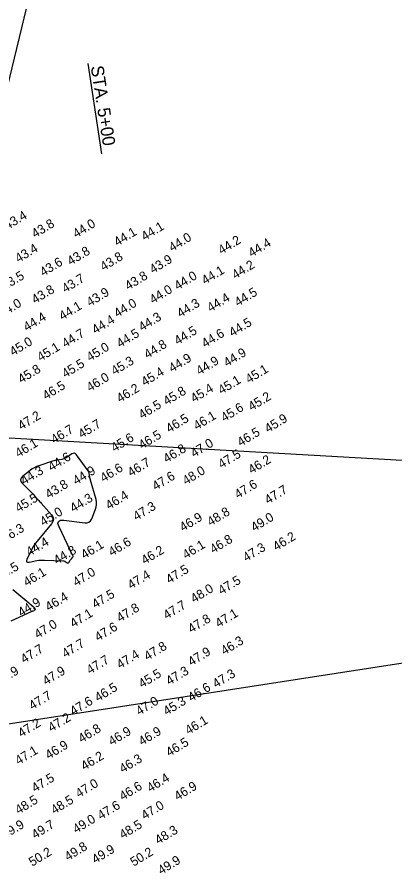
# Model space of a CAD drawing. Extents: x 415488 to 419888, y 1187739 to 1191312.
# Drawn here: x 417516 to 417929, y 1189587 to 1190515 of the extents above; entities that cross this region are included whole.
import ezdxf

# ---------------------------------------------------------------- set-up
doc = ezdxf.new("R2010")
doc.units = 0
for name, color, linetype in [('C-CHAN-POIT', 7, 'Continuous'), ('C-CHAN-WIDE', 7, 'Continuous'), ('V-ALGN-TEXT', 7, 'Continuous'), ('V-TOPO-MAJR', 7, 'Continuous'), ('V-TOPO-SOUN', 7, 'Continuous')]:
    doc.layers.add(name, color=color, linetype=linetype)

msp = doc.modelspace()

# ---------------------------------------------------------------- linework, layer by layer
at = {"layer": 'C-CHAN-POIT'}
msp.add_line((417394.74, 1189724.92), (418985.51, 1189971.03), dxfattribs=at)
at = {"layer": 'C-CHAN-WIDE'}
msp.add_line((416205.49, 1190128.89), (418985.51, 1189971.03), dxfattribs=at)
at = {"layer": 'V-ALGN-TEXT'}
for p, q in [((417252.51, 1189399.35), (417536.93, 1190565.61)), ((417593.74, 1190464.04), (417609.03, 1190365.21))]:
    msp.add_line(p, q, dxfattribs=at)
at = {"layer": 'V-TOPO-MAJR'}
msp.add_lwpolyline([(417596.14, 1190011.22), (417596.09, 1190011.47), (417596.04, 1190011.73), (417595.36, 1190015.86), (417595.2, 1190016.62), (417594.94, 1190017.34), (417594.61, 1190018.03), (417594.19, 1190018.68), (417581.35, 1190036.38), (417580.3, 1190037.46), (417579.14, 1190037.98), (417577.87, 1190037.92), (417576.5, 1190037.28), (417570.09, 1190033.16), (417568.99, 1190032.52), (417567.83, 1190032), (417566.63, 1190031.6), (417565.38, 1190031.33), (417560.3, 1190030.47), (417559.03, 1190030.23), (417557.77, 1190029.95), (417556.53, 1190029.62), (417555.3, 1190029.24), (417540.16, 1190024.36), (417537.65, 1190023.42), (417535.27, 1190022.27), (417533, 1190020.9), (417530.85, 1190019.31), (417522.47, 1190012.53), (417520.88, 1190010.81), (417520.28, 1190009.04), (417520.69, 1190007.21), (417522.09, 1190005.33), (417531.95, 1189995.47), (417532.9, 1189994.5), (417533.84, 1189993.53), (417534.76, 1189992.53), (417535.67, 1189991.53), (417539.27, 1189987.49), (417540.17, 1189986.48), (417541.07, 1189985.47), (417541.97, 1189984.46), (417542.87, 1189983.45), (417554.04, 1189970.89), (417555.67, 1189968.45), (417556.24, 1189966), (417555.75, 1189963.52), (417554.2, 1189961.03), (417538.31, 1189941.95), (417536.64, 1189939.83), (417535.12, 1189937.62), (417533.73, 1189935.32), (417532.48, 1189932.93), (417527.25, 1189922.2), (417526.69, 1189920.56), (417526.9, 1189919.49), (417527.87, 1189919.01), (417529.6, 1189919.1), (417538.07, 1189920.64), (417540.19, 1189920.97), (417542.32, 1189921.17), (417544.46, 1189921.26), (417546.6, 1189921.23), (417567.09, 1189920.4), (417567.67, 1189920.33), (417568.23, 1189920.19), (417568.76, 1189919.97), (417569.27, 1189919.68), (417571.25, 1189918.34), (417571.72, 1189918.1), (417572.16, 1189918.08), (417572.57, 1189918.25), (417572.94, 1189918.63), (417574.67, 1189921.02), (417574.97, 1189921.44), (417575.29, 1189921.84), (417575.61, 1189922.24), (417575.95, 1189922.64), (417577.3, 1189924.19), (417577.57, 1189924.58), (417577.7, 1189925), (417577.69, 1189925.44), (417577.53, 1189925.89), (417562.45, 1189957.46), (417561.25, 1189961.13), (417561.74, 1189963.59), (417563.91, 1189964.82), (417567.78, 1189964.83), (417590.48, 1189961.93), (417593.04, 1189961.94), (417595.17, 1189962.7), (417596.86, 1189964.19), (417598.12, 1189966.43), (417602.29, 1189976.84), (417603.11, 1189979.46), (417603.47, 1189982.1), (417603.39, 1189984.77), (417602.86, 1189987.46), (417596.9, 1190008.74), (417596.83, 1190008.99), (417596.76, 1190009.24), (417596.68, 1190009.49), (417596.6, 1190009.73), (417596.28, 1190010.72), (417596.21, 1190010.97)], close=True, dxfattribs=at)
msp.add_lwpolyline([(417511.83, 1189889.14), (417529.23, 1189874.49), (417529.79, 1189874.02), (417530.35, 1189873.55), (417530.92, 1189873.08), (417531.48, 1189872.61), (417534.31, 1189870.25), (417534.57, 1189870.01), (417534.81, 1189869.76), (417535.03, 1189869.5), (417535.23, 1189869.21), (417536.09, 1189867.85), (417536.19, 1189867.65), (417536.22, 1189867.45), (417536.17, 1189867.26), (417536.07, 1189867.06), (417535.49, 1189866.29), (417535.34, 1189866.11), (417535.16, 1189865.97), (417534.97, 1189865.85), (417534.75, 1189865.76), (417533.57, 1189865.39), (417533.29, 1189865.3), (417533.02, 1189865.2), (417532.76, 1189865.09), (417532.5, 1189864.97), (417509.81, 1189854.42)], dxfattribs=at)

# ---------------------------------------------------------------- texts
at = {"layer": 'V-ALGN-TEXT'}
msp.add_text('STA. 5+00', height=13.92, rotation=278.79434, dxfattribs=at).set_placement((417597.07, 1190460.78))
at = {"layer": 'V-TOPO-SOUN'}
for s, p in [('43.4 ', (417506.09, 1190281.99)), ('43.8 ', (417536.1, 1190273)), ('44.0 ', (417581.09, 1190273)), ('44.1 ', (417656.08, 1190269.98)), ('44.1 ', (417626.1, 1190263.97)), ('44.0 ', (417686.1, 1190257.97)), ('44.2 ', (417740.11, 1190254.98)), ('44.4 ', (417773.08, 1190252)), ('43.4 ', (417518.09, 1190245.99)), ('43.8 ', (417575.08, 1190242.98)), ('43.6 ', (417545.09, 1190230.97)), ('43.8 ', (417611.1, 1190236.97)), ('43.9 ', (417665.11, 1190233.99)), ('44.1 ', (417722.1, 1190221.98)), ('44.2 ', (417755.1, 1190227.98)), ('43.5 ', (417503.1, 1190215.97)), ('43.7 ', (417569.11, 1190212.99)), ('43.8 ', (417638.11, 1190215.97)), ('44.0 ', (417692.11, 1190215.97)), ('43.8 ', (417536.1, 1190200.98)), ('44.0 ', (417665.11, 1190200.98)), ('43.9 ', (417596.08, 1190198)), ('44.4 ', (417728.1, 1190191.99)), ('44.5 ', (417758.09, 1190198)), ('44.0 ', (417500.08, 1190185.99)), ('44.1 ', (417566.09, 1190182.97)), ('44.0 ', (417626.1, 1190185.99)), ('44.3 ', (417695.09, 1190185.99)), ('44.4 ', (417527.08, 1190170.99)), ('44.4 ', (417602.08, 1190167.98)), ('44.3 ', (417653.1, 1190170.99)), ('44.5 ', (417752.08, 1190164.99)), ('44.5 ', (417692.11, 1190155.97)), ('44.7 ', (417569.11, 1190152.98)), ('44.5 ', (417629.08, 1190152.98)), ('44.6 ', (417722.1, 1190152.98)), ('45.0 ', (417512.09, 1190143.99)), ('45.1 ', (417542.11, 1190137.99)), ('45.0 ', (417596.08, 1190137.99)), ('44.8 ', (417659.1, 1190140.98)), ('44.9 ', (417746.08, 1190131.99)), ('45.5 ', (417569.11, 1190119.98)), ('45.3 ', (417623.08, 1190123)), ('44.9 ', (417686.1, 1190125.98)), ('44.9 ', (417716.09, 1190123)), ('45.8 ', (417521.08, 1190113.97)), ('45.4 ', (417656.08, 1190110.99)), ('45.1 ', (417770.09, 1190113.97)), ('46.0 ', (417596.08, 1190104.98)), ('45.1 ', (417740.11, 1190102)), ('46.5 ', (417548.08, 1190095.99)), ('46.2 ', (417629.08, 1190092.98)), ('45.8 ', (417680.1, 1190089.99)), ('45.4 ', (417710.09, 1190092.98)), ('45.2 ', (417773.08, 1190083.99)), ('46.5 ', (417653.1, 1190075)), ('45.6 ', (417743.09, 1190071.98)), ('47.2 ', (417521.08, 1190062.99)), ('46.1 ', (417713.11, 1190062.99)), ('45.7 ', (417587.09, 1190053.97)), ('46.5 ', (417683.09, 1190059.97)), ('45.9 ', (417791.09, 1190059.97)), ('46.7 ', (417557.1, 1190048)), ('46.5 ', (417761.1, 1190044.98)), ('45.6 ', (417623.08, 1190038.97)), ('46.5 ', (417653.1, 1190041.99)), ('46.1 ', (417518.09, 1190032.97)), ('46.8 ', (417680.1, 1190026.97)), ('47.0 ', (417710.09, 1190032.97)), ('44.6 ', (417554.08, 1190017.98)), ('47.5 ', (417740.11, 1190021)), ('46.2 ', (417773.08, 1190014.99)), ('46.6 ', (417611.1, 1190005.97)), ('46.7 ', (417641.09, 1190011.97)), ('44.3 ', (417524.1, 1190002.98)), ('44.9 ', (417581.09, 1190002.98)), ('47.6 ', (417668.09, 1189996.98)), ('48.0 ', (417701.1, 1190002.98)), ('43.8 ', (417551.1, 1189987.99)), ('47.6 ', (417758.09, 1189987.99)), ('47.7 ', (417791.09, 1189981.99)), ('45.5 ', (417518.09, 1189973)), ('44.3 ', (417578.1, 1189973)), ('46.4 ', (417617.11, 1189975.98)), ('47.3 ', (417647.1, 1189963.97)), ('45.0 ', (417545.09, 1189957.97)), ('46.9 ', (417698.08, 1189951.97)), ('48.8 ', (417728.1, 1189957.97)), ('49.0 ', (417776.1, 1189951.97)), ('46.3 ', (417503.1, 1189939.99)), ('44.4 ', (417530.1, 1189925)), ('46.6 ', (417620.09, 1189925)), ('46.8 ', (417731.08, 1189927.98)), ('46.2 ', (417800.08, 1189930.97)), ('44.8 ', (417560.09, 1189915.98)), ('46.1 ', (417590.11, 1189921.98)), ('46.2 ', (417656.08, 1189915.98)), ('46.1 ', (417701.1, 1189921.98)), ('47.3 ', (417767.11, 1189918.99)), ('45.5 ', (417497.1, 1189898)), ('47.5 ', (417683.09, 1189894.98)), ('46.1 ', (417527.08, 1189891.99)), ('47.0 ', (417581.09, 1189891.99)), ('47.4 ', (417641.09, 1189888.97)), ('47.5 ', (417740.11, 1189882.97)), ('47.5 ', (417602.08, 1189867.98)), ('48.0 ', (417710.09, 1189873.98)), ('44.9 ', (417521.08, 1189858.99)), ('46.4 ', (417551.1, 1189864.99)), ('47.8 ', (417629.08, 1189852.98)), ('47.7 ', (417680.1, 1189855.97)), ('47.1 ', (417578.1, 1189846.98)), ('47.8 ', (417707.1, 1189840.98)), ('47.1 ', (417737.09, 1189846.98)), ('47.0 ', (417539.09, 1189834.97)), ('47.6 ', (417605.1, 1189831.99)), ('47.7 ', (417569.11, 1189813.97)), ('47.8 ', (417659.1, 1189810.99)), ('46.3 ', (417743.09, 1189816.99)), ('47.7 ', (417524.1, 1189807.97)), ('47.4 ', (417629.08, 1189801.97)), ('47.9 ', (417707.1, 1189804.98)), ('47.7 ', (417596.08, 1189796)), ('47.9 ', (417497.1, 1189783.99)), ('47.9 ', (417548.08, 1189783.99)), ('47.3 ', (417683.09, 1189783.99)), ('45.5 ', (417653.1, 1189780.97)), ('47.3 ', (417734.1, 1189780.97)), ('46.5 ', (417605.1, 1189765.98)), ('46.6 ', (417707.1, 1189765.98)), ('47.7 ', (417533.09, 1189756.99)), ('47.6 ', (417578.1, 1189750.98)), ('47.0 ', (417650.08, 1189750.98)), ('45.3 ', (417680.1, 1189750.98)), ('47.2 ', (417554.08, 1189732.97)), ('46.1 ', (417704.08, 1189729.99)), ('47.2 ', (417521.08, 1189726.97)), ('46.8 ', (417587.09, 1189721)), ('46.9 ', (417620.09, 1189717.98)), ('46.9 ', (417653.1, 1189717.98)), ('46.9 ', (417551.1, 1189702.98)), ('46.5 ', (417683.09, 1189705.97)), ('47.1 ', (417518.09, 1189696.98)), ('46.2 ', (417590.11, 1189690.98)), ('46.3 ', (417632.1, 1189687.99)), ('47.5 ', (417536.1, 1189666.99)), ('46.4 ', (417662.09, 1189666.99)), ('47.0 ', (417584.1, 1189660.99)), ('46.6 ', (417632.1, 1189657.97)), ('46.9 ', (417692.11, 1189657.97)), ('48.5 ', (417518.09, 1189642.98)), ('48.5 ', (417557.1, 1189642.98)), ('47.6 ', (417608.09, 1189636.97)), ('47.0 ', (417656.08, 1189636.97)), ('49.9 ', (417503.1, 1189615.98)), ('49.7 ', (417536.1, 1189615.98)), ('49.0 ', (417581.09, 1189621.98)), ('48.5 ', (417632.1, 1189615.98)), ('48.3 ', (417671.08, 1189609.97)), ('49.8 ', (417572.1, 1189591.99)), ('49.9 ', (417602.08, 1189588.97)), ('50.2 ', (417533.09, 1189585.99)), ('50.2 ', (417644.11, 1189585.99)), ('49.9 ', (417674.1, 1189576.97))]:
    msp.add_text(s, height=9.996, rotation=31.2939, dxfattribs=at).set_placement(p)

doc.saveas('drawing.dxf')
